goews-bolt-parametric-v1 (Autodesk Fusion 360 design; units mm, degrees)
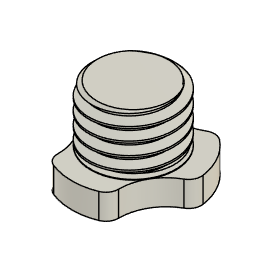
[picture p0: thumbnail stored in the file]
parameter "Boltlength" = 9
cylinder_primitive "CylinderPrimitive1" Height 9 (= "Boltlength") Diameter 14
thread "Thread1" ThreadOffset 0.1 ThreadLength 8.9 (= "Boltlength - 0.1 mm")
chamfer "Chamfer1" distance 1
sketch "Head" plane through (0, 0, 0) normal (0, 0, -1) x axis (1, 0, 0)
  line L1 (0, 9.761) -> (0, -9.761)
  line L2 (1, -7) -> (-1, 7)
  line L3 (-1, -7) -> (1, 7)
  line L4 (-9.761, 0) -> (9.761, 0)
  line L5 (0, -6.761) -> (0, 6.761)
  line L6 (0, 14) -> (0, -14)
  line L7 (-14.605, 18) -> (13.3677, 18)
  line L8 (0, 9.761) -> (0, -9.761)
  line L9 (6, -9.761) -> (0, -9.761)
  line L10 (0, -9.761) -> (6, -9.761)
  line L11 (-6, -9.761) -> (0, -9.761)
  circle C1 centre (0, 0) radius 6.761
  circle C2 centre (0, 0) radius 9.761
  arc A1 centre (0, -14.261) radius 7.5 clockwise from (-6, -9.761) to (6, -9.761)
  arc A2 centre (12.3504, 7.1305) radius 7.5 clockwise from (11.4533, -0.3157) to (5.4533, 10.0767)
  arc A3 centre (-12.3504, 7.1305) radius 7.5 clockwise from (-5.4533, 10.0767) to (-11.4533, -0.3157)
  point P5 (0, 9.761)
  point P4 (0, -9.761)
  point P10 (0, 0)
  point P2 (0, 0)
  point P12 (-9.761, 0)
  point P11 (9.761, 0)
  point P14 (0, -6.761)
  point P15 (0, 0)
  point P18 (0, 0)
  point P22 (0, 9.761)
  point P23 (0, 0)
  point P8 (1, -7)
  point P9 (-1, -7)
  point P7 (1, 7)
  point P13 (0, 6.761)
  point P16 (0, -14)
  point P17 (0, 14)
  point P21 (0, -9.761)
  point P24 (6, -9.761)
  point P25 (-6, -9.761)
  coincident C2 P5
  vertical L1
  coincident C2 P4
  coincident L2 P10
  coincident L3 P10
  coincident P2 P10
  coincident C2 P12
  coincident C2 P11
  coincident L1 P14
  coincident C1 P14
  coincident P10 P15
  midpoint L5 P15
  parallel L1 L6
  coincident P15 P18
  midpoint L6 P18
  coincident P5 P22
  parallel L1 L8
  coincident P18 P23
  midpoint L8 P23
  perpendicular L1 L9
  perpendicular L8 L11
  coincident P14 A1
  dimension "d7" = 3
  dimension "d9" distance P8 P9 = 2
  dimension "d10" distance P7 P8 = 14
  dimension "d25" distance P13 P14 = 13.522
  dimension "d27" distance P16 P17 = 28
  dimension "d28" distance P10 L7 = 18
  dimension "d33" distance P21 P24 = 6
  dimension "d34" distance P4 P25 = 6
  dimension "d36" value = 360 (= "C-Pattern1-Angle")
extrude "Extrude1" add sketch "Head" profile of C1 C2 A1 A2 A3 along normal blind 4
fillet "Fillet1" radius 2
sketch "Sketch4" plane through (0, 0, -4) normal (0, 0, -1) x axis (1, 0, 0)
  line L1 (4.8494, 0.0536) -> (2.4711, -4.173)
  line L2 (2.3783, 4.2265) -> (4.8494, 0.0536)
  line L3 (-2.4711, 4.173) -> (2.3783, 4.2265)
  line L4 (-4.8494, -0.0536) -> (-2.4711, 4.173)
  line L5 (-2.3783, -4.2265) -> (-4.8494, -0.0536)
  line L6 (2.4711, -4.173) -> (-2.3783, -4.2265)
  arc A1 centre (-7.6768, -1.1404) radius 2 clockwise from (-9.6551, -1.4342) to (-8.6607, 0.6009)
  arc A2 centre (0, 0) radius 9.761 clockwise from (-6.0696, -7.6444) to (-9.6551, -1.4342)
  arc A3 centre (-4.826, -6.0781) radius 2 clockwise from (-3.81, -7.8008) to (-6.0696, -7.6444)
  arc A4 centre (0, -14.261) radius 7.5 clockwise from (-3.81, -7.8008) to (3.81, -7.8008)
  arc A5 centre (4.826, -6.0781) radius 2 clockwise from (6.0696, -7.6444) to (3.81, -7.8008)
  arc A6 centre (0, 0) radius 9.761 clockwise from (9.6551, -1.4342) to (6.0696, -7.6444)
  arc A7 centre (7.6768, -1.1404) radius 2 clockwise from (8.6607, 0.6009) to (9.6551, -1.4342)
  arc A8 centre (12.3504, 7.1305) radius 7.5 clockwise from (8.6607, 0.6009) to (4.8507, 7.1999)
  arc A9 centre (2.8508, 7.2185) radius 2 clockwise from (3.5854, 9.0786) to (4.8507, 7.1999)
  arc A10 centre (0, 0) radius 9.761 clockwise from (-3.5854, 9.0786) to (3.5854, 9.0786)
  arc A11 centre (-2.8508, 7.2185) radius 2 clockwise from (-4.8507, 7.1999) to (-3.5854, 9.0786)
  arc A12 centre (-12.3504, 7.1305) radius 7.5 clockwise from (-4.8507, 7.1999) to (-8.6607, 0.6009)
  point P6 (0, 0)
  point P30 (0, 0)
  coincident P6 P30
  dimension "d39" distance P30 L6 = 4.2
extrude "Extrude6" cut sketch "Sketch4" profile of L1 L2 L3 L4 L5 L6 against normal blind 3.5
chamfer "Chamfer6" distance 0.5
named bodies: "Bolt"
